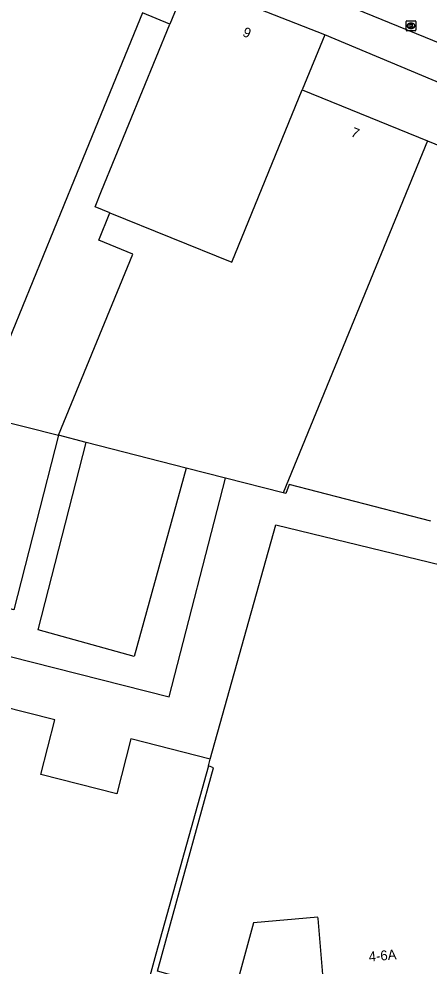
# Model space of a CAD drawing. Extents: x 160557 to 161245, y 385330 to 386505.
# Drawn here: x 160919 to 160960.7, y 385636 to 385732.3 of the extents above; entities that cross this region are included whole.
import ezdxf

# ---------------------------------------------------------------- set-up
doc = ezdxf.new("R2010")
doc.units = 0
for name, color, linetype in [('IMGEO_Hek', 7, 'Continuous'), ('IMGEO_Kolk', 7, 'Continuous'), ('IMGEO_Pand', 7, 'Continuous'), ('IMGEO_Pand_nummerreeks', 7, 'Continuous'), ('IMGEO_Parkeervlak_open', 7, 'Continuous'), ('IMGEO_Rijbaan_lokaal_gesloten', 7, 'Continuous'), ('IMGEO_Voetpad_open', 7, 'Continuous')]:
    doc.layers.add(name, color=color, linetype=linetype)

msp = doc.modelspace()

# ---------------------------------------------------------------- linework, layer by layer
at = {"layer": 'IMGEO_Hek'}
msp.add_lwpolyline([(160934.375, 385731.796), (160931.608, 385732.931)], dxfattribs=at)
at = {"layer": 'IMGEO_Kolk'}
for p, q in [((160958.409, 385731.193), (160958.409, 385732.045)), ((160958.484, 385732.119), (160959.336, 385732.119)), ((160958.92, 385731.339), (160958.895, 385731.339)), ((160958.897, 385731.899), (160958.922, 385731.899)), ((160959.41, 385732.045), (160959.41, 385731.193)), ((160959.336, 385731.119), (160958.484, 385731.119))]:
    msp.add_line(p, q, dxfattribs=at)
for points in [[(160958.409, 385731.193), (160958.409, 385732.045)], [(160958.484, 385732.119), (160959.336, 385732.119)], [(160958.73, 385731.819), (160958.853, 385731.819), (160958.853, 385731.668), (160958.983, 385731.819), (160959.147, 385731.819), (160959.001, 385731.668), (160959.154, 385731.419), (160959.002, 385731.419), (160958.917, 385731.583), (160958.853, 385731.516), (160958.853, 385731.419), (160958.73, 385731.419), (160958.73, 385731.819)], [(160959.41, 385732.045), (160959.41, 385731.193)], [(160959.336, 385731.119), (160958.484, 385731.119)]]:
    msp.add_lwpolyline(points, dxfattribs=at)
for centre, start, end in [((160958.486, 385732.043), 91.55205, 178.44795), ((160958.486, 385732.043), 91.55205, 178.44795), ((160959.334, 385732.043), 1.55205, 88.44795), ((160959.334, 385732.043), 1.55205, 88.44795), ((160958.486, 385731.195), 181.55205, 268.44795), ((160958.486, 385731.195), 181.55205, 268.44795), ((160959.334, 385731.195), 271.55205, 358.44795), ((160959.334, 385731.195), 271.55205, 358.44795)]:
    msp.add_arc(centre, 0.0765, start, end, dxfattribs=at)
for centre, major_axis, ratio, start_param, end_param in [((160958.896, 385731.619), (-0.387, 0.002), 0.722429, 4.712389, 7.853982), ((160958.921, 385731.619), (-0.39, 0.002), 0.717154, 1.570796, 4.712389)]:
    msp.add_ellipse(centre, major_axis=major_axis, ratio=ratio, start_param=start_param, end_param=end_param, dxfattribs=at)
at = {"layer": 'IMGEO_Pand'}
for points in [[(160936.171, 385736.193), (160934.375, 385731.796)], [(160950.143, 385730.7), (160936.171, 385736.193)], [(160931.608, 385732.931), (160924.649, 385715.965), (160916.201, 385695.359), (160911.867, 385697.136)], [(160928.292, 385712.609), (160926.791, 385713.221), (160927.445, 385714.823), (160934.375, 385731.796)], [(160950.143, 385730.7), (160947.854, 385725.093)], [(160928.292, 385712.609), (160940.674, 385707.564), (160947.854, 385725.093)], [(160947.854, 385725.093), (160960.586, 385719.902)], [(160960.586, 385719.902), (160945.896, 385684.109)], [(160960.586, 385719.902), (160974.303, 385714.31)], [(160923.046, 385689.973), (160930.614, 385708.401), (160927.151, 385709.814), (160928.292, 385712.609)], [(160925.871, 385689.248), (160923.046, 385689.973)], [(160936.043, 385686.638), (160925.871, 385689.248)], [(160940.041, 385685.612), (160936.043, 385686.638)], [(160945.896, 385684.109), (160940.041, 385685.612)], [(160960.913, 385681.247), (160946.512, 385684.958), (160946.173, 385684.038), (160945.896, 385684.109)], [(160938.493, 385657.051), (160945.182, 385680.878), (160966.78, 385675.609)], [(160938.493, 385657.051), (160930.406, 385659.095), (160928.995, 385653.511), (160921.278, 385655.462), (160922.689, 385661.046), (160900.548, 385666.641)], [(160938.325, 385656.372), (160932.953, 385637.194), (160931.641, 385632.369)], [(160968.714, 385653.444), (160968.005, 385653.367), (160968.951, 385642.66), (160963.319, 385642.172), (160963.939, 385635.17), (160964.1, 385635.164), (160964.134, 385634.743), (160949.94, 385633.511), (160949.904, 385633.932), (160950.055, 385633.931), (160949.455, 385640.834), (160949.443, 385640.975), (160942.91, 385640.389), (160941.064, 385633.675), (160941.217, 385633.639), (160941.099, 385633.233), (160933.113, 385635.47), (160934.444, 385640.29), (160938.817, 385656.14), (160938.325, 385656.372)], [(160938.325, 385656.372), (160938.493, 385657.051)]]:
    msp.add_lwpolyline(points, dxfattribs=at)
at = {"layer": 'IMGEO_Parkeervlak_open'}
for points in [[(160934.375, 385731.796), (160931.608, 385732.931)], [(160915.534, 385688.79), (160916.316, 385691.691), (160923.046, 385689.973)], [(160923.046, 385689.973), (160918.514, 385672.216), (160911.571, 385674.088)], [(160936.043, 385686.638), (160930.753, 385667.48), (160920.977, 385670.179), (160925.871, 385689.248)], [(160900.548, 385666.641), (160901.809, 385671.613), (160934.332, 385663.363), (160940.041, 385685.612)]]:
    msp.add_lwpolyline(points, dxfattribs=at)
at = {"layer": 'IMGEO_Rijbaan_lokaal_gesloten'}
msp.add_lwpolyline([(160877.824, 385767.253), (160909.425, 385751.357), (160913.773, 385749.567), (160937.4, 385739.851), (160999.849, 385714.356), (161010.829, 385709.873)], dxfattribs=at)
at = {"layer": 'IMGEO_Voetpad_open'}
msp.add_lwpolyline([(161009.232, 385705.924), (160999.817, 385709.872), (160990.673, 385713.706), (160950.143, 385730.7)], dxfattribs=at)

# ---------------------------------------------------------------- texts
at = {"layer": 'IMGEO_Pand_nummerreeks'}
for s, rotation, p in [('9', 337.78643, (160941.699, 385730.605)), ('7', 337.8208, (160952.717, 385720.411)), ('4-6A', 4.96068, (160954.652, 385636.449))]:
    msp.add_text(s, height=1, rotation=rotation, dxfattribs=at).set_placement(p)

doc.saveas('drawing.dxf')
